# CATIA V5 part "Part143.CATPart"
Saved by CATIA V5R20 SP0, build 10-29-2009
Part number: FA 105700-1
Revision: ANY
Definition: UNKNOWN
Nomenclature: FA 105700-1
Source: Unknown
Bounding box of the stored display mesh (mm): x -2.853 to 2.853, y 0.2 to 2.5, z -3 to 3
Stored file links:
  C:\Users\Utente\Desktop\IO LAVORO\3D X SITO CF\CUMSA\3D files FA\FA 105700\Part143.CATPart

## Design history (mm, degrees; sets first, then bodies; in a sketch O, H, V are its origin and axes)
Body1 "Cortar-Extruir1" (main body)
  Solid1: solid without history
